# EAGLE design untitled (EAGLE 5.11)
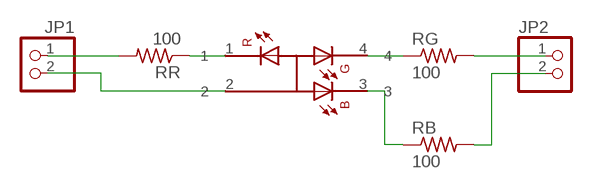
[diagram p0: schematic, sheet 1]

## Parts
JP1  PINHD-1X2  [1X02]
JP2  PINHD-1X2  [1X02]
RB  100  R-US_R1210  [R1210]
RG  100  R-US_R1210  [R1210]
RR  100  R-US_R1210  [R1210]
U$1  LED-RGB-PLCC-SMD  [PLCC4-RGB-LED]

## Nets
N$1: JP1.2 U$1.2
N$2: RR.1 U$1.1
N$4: JP2.1 RG.2
N$5: RB.1 U$1.3
N$6: RG.1 U$1.4
N$7: JP2.2 RB.2
N$8: JP1.1 RR.2

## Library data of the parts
JP1 JP2 = pinhead:PINHD-1X2: PIN HEADER
RB RG RR = resistor:R-US_: RESISTOR, American symbol
U$1 = trl:LED-RGB-PLCC-SMD

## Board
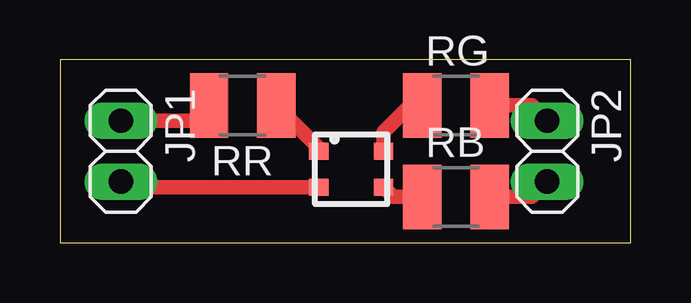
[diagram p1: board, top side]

Size 23.8 x 7.61 mm. Coordinates in mm from the lower left corner, seen from the top.
Outline: 0,0 23.8,0 23.8,7.61 0,7.61 0,0
Copper layers (1*16): Top 0.035mm / dielectric 1.5mm / Bottom 0.035mm
Design rules "default": minimum track width 10mil, minimum drill 0.6mm, track to track 8mil, track to pad 8mil, pad to pad 8mil, via to via 8mil, smd to smd 8mil, copper to edge 40mil, drill to drill 8mil, minimum pad ring 10mil, minimum via ring 8mil, stop-mask expansion 4mil, vias tented up to drill 0mil, thermal gap 10mil

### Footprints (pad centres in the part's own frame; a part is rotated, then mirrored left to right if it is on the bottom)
1X02 = drill 1.016 long: 1 -1.27,0; 2 1.27,0
R1210 = smd 1.6 x 2.7: 1 -1.4,0; 2 1.4,0
PLCC4-RGB-LED = smd 0.8 x 0.7: 1 0,0; 2 0,-1.5; 3 2.7,-1.5; 4 2.7,0

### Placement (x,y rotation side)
JP1  2.54,3.81 270 top
JP2  20.32,3.81 270 top
RB  16.51,1.91 0 top
RG  16.51,5.71 0 top
RR  7.62,5.71 180 top
U$1  10.79,3.81 0 top

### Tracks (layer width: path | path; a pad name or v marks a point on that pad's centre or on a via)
N$1
  Top 0.61: U$1.2 2.77,2.31 JP1.2
N$2
  Top 0.61: U$1.1 10.79,3.94 RR.1
N$4
  Top 0.61: RG.2 19.68,5.71 JP2.1
N$5
  Top 0.61: RB.1 13.9,1.91 U$1.3
N$6
  Top 0.61: U$1.4 13.49,4.61 15.24,6.35 15.24,5.84 RG.1
N$7
  Top 0.61: RB.2 19.68,1.91 JP2.2
N$8
  Top 0.61: JP1.1 5.58,5.08 RR.2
